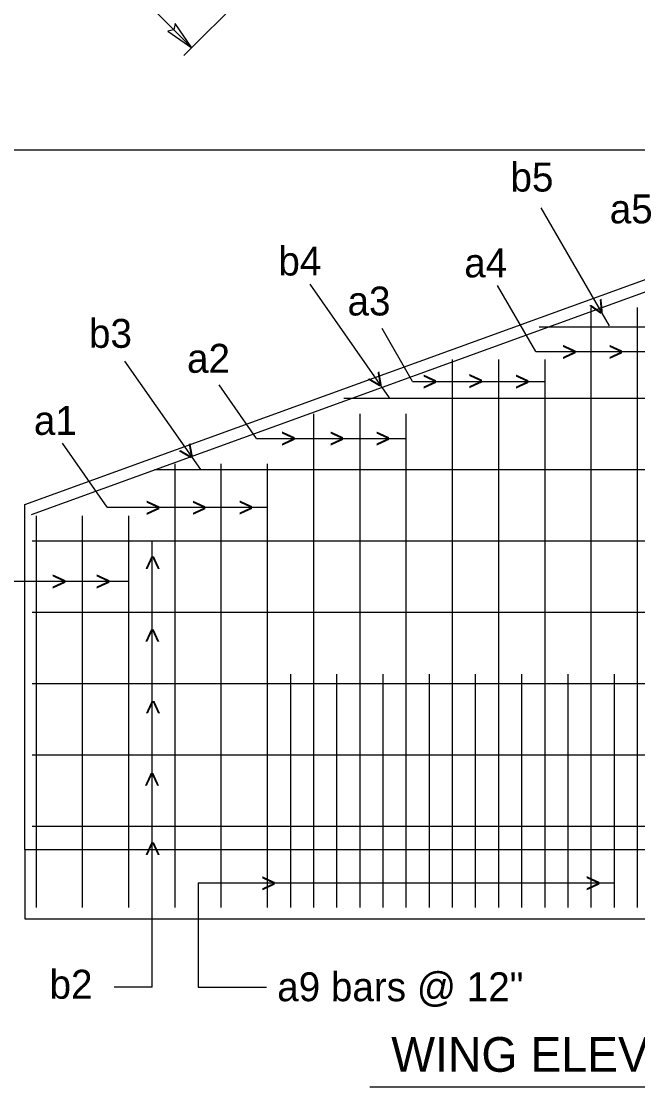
# Model space of a CAD drawing. Extents: x -0.08 to 2.83, y -0.03 to 1.92.
# Drawn here: x 0.368 to 0.6457, y 0.5697 to 1.0496 of the extents above; entities that cross this region are included whole.
import ezdxf

# ---------------------------------------------------------------- set-up
doc = ezdxf.new("R2010")
doc.units = 0
for name, color, linetype in [('50', 7, 'Continuous'), ('51', 7, 'Continuous'), ('54', 7, 'Continuous'), ('55', 7, 'Continuous'), ('57', 7, 'Continuous')]:
    doc.layers.add(name, color=color, linetype=linetype)

msp = doc.modelspace()

# ---------------------------------------------------------------- linework, layer by layer
at = {"layer": '50'}
for p, q in [((0.36955, 0.83186), (0.80997, 0.99159)), ((0.37249, 0.82739), (0.81676, 0.98851)), ((0.36955, 0.67649), (0.36955, 0.83186)), ((0.36955, 0.67649), (0.36955, 0.64524)), ((0.36955, 0.67649), (0.91992, 0.67649)), ((0.36955, 0.64524), (0.88809, 0.64524))]:
    msp.add_line(p, q, dxfattribs=at)
at = {"layer": '51'}
for p, q in [((0.62476, 0.65044), (0.62476, 0.92069)), ((0.64559, 0.65044), (0.64559, 0.92069)), ((0.81864, 0.91172), (0.60129, 0.91172)), ((0.56226, 0.65044), (0.56226, 0.89728)), ((0.58309, 0.65044), (0.58309, 0.89728)), ((0.60393, 0.65044), (0.60393, 0.89728)), ((0.81864, 0.8796), (0.51335, 0.8796)), ((0.49976, 0.65044), (0.49976, 0.87278)), ((0.52059, 0.65044), (0.52059, 0.87278)), ((0.54143, 0.65044), (0.54143, 0.87278)), ((0.43726, 0.65044), (0.43726, 0.85016)), ((0.45809, 0.65044), (0.45809, 0.85016)), ((0.47893, 0.65044), (0.47893, 0.85016)), ((0.81864, 0.84749), (0.42799, 0.84749)), ((0.37476, 0.65044), (0.37476, 0.82688)), ((0.39559, 0.65044), (0.39559, 0.82688)), ((0.41643, 0.65044), (0.41643, 0.82688)), ((0.81864, 0.81537), (0.37281, 0.81537)), ((0.81864, 0.78324), (0.37281, 0.78324)), ((0.48934, 0.65044), (0.48934, 0.75553)), ((0.51018, 0.65044), (0.51018, 0.75553)), ((0.53101, 0.65044), (0.53101, 0.75553)), ((0.55184, 0.65044), (0.55184, 0.75553)), ((0.57268, 0.65044), (0.57268, 0.75553)), ((0.59351, 0.65044), (0.59351, 0.75553)), ((0.61434, 0.65044), (0.61434, 0.75553)), ((0.63518, 0.65044), (0.63518, 0.75553)), ((0.81864, 0.75113), (0.37281, 0.75113)), ((0.81864, 0.71901), (0.37281, 0.71901)), ((0.81864, 0.68689), (0.37281, 0.68689))]:
    msp.add_line(p, q, dxfattribs=at)
at = {"layer": '54'}
msp.add_lwpolyline([(0.44481, 1.03767), (0.4373, 1.04853), (0.43669, 1.04579), (0.43403, 1.04505)], close=True, dxfattribs=at)
at = {"layer": '55'}
for p, q in [((0.32327, 1.1592), (0.44481, 1.03767)), ((0.49826, 1.09112), (0.44123, 1.03409)), ((0.79701, 0.99159), (0.27695, 0.99159)), ((0.63299, 0.91234), (0.60224, 0.96558)), ((0.53391, 0.87999), (0.49814, 0.93109)), ((0.59977, 0.90078), (0.58259, 0.93055)), ((0.54424, 0.88736), (0.53053, 0.91112)), ((0.59977, 0.90078), (0.66659, 0.90078)), ((0.44883, 0.84765), (0.41465, 0.89648)), ((0.474, 0.86169), (0.45709, 0.88584)), ((0.54424, 0.88736), (0.60393, 0.88736)), ((0.40664, 0.83074), (0.3865, 0.8595)), ((0.474, 0.86169), (0.54143, 0.86169)), ((0.40664, 0.83074), (0.47878, 0.83074)), ((0.42697, 0.61445), (0.42697, 0.81537)), ((0.34383, 0.79741), (0.41597, 0.79741)), ((0.44764, 0.6615), (0.44764, 0.61445)), ((0.44764, 0.6615), (0.63518, 0.6615)), ((0.42697, 0.61445), (0.40988, 0.61445)), ((0.44764, 0.61445), (0.47843, 0.61445))]:
    msp.add_line(p, q, dxfattribs=at)
at = {"layer": '57'}
msp.add_line((0.52505, 0.56966), (0.74916, 0.56966), dxfattribs=at)

# ---------------------------------------------------------------- texts
at = {"layer": '55'}
for height, rotation, p in [(0.00867, 299.9951, (0.62274, 0.92144)), (0.00867, 299.9951, (0.62274, 0.92144)), (0.00867, 299.9951, (0.62274, 0.92144)), (0.00867, 299.9951, (0.62274, 0.92144)), (0.00867, 304.992, (0.52289, 0.88818)), (0.00867, 304.992, (0.52289, 0.88818)), (0.00867, 304.992, (0.52289, 0.88818)), (0.00867, 304.992, (0.52289, 0.88818)), (0.00867, 304.992, (0.43781, 0.85584)), (0.00867, 304.992, (0.43781, 0.85584)), (0.00868, 90, (0.4313, 0.80235)), (0.00868, 90, (0.4313, 0.80235)), (0.00868, 90, (0.43116, 0.7695)), (0.00868, 90, (0.43116, 0.7695)), (0.00868, 90, (0.43145, 0.73725)), (0.00868, 90, (0.43145, 0.73725)), (0.00868, 90, (0.43101, 0.70471)), (0.00868, 90, (0.43101, 0.70471)), (0.00868, 90, (0.43129, 0.67352)), (0.00868, 90, (0.43129, 0.67352))]:
    msp.add_text('>', height=height, rotation=rotation, dxfattribs=at).set_placement(p)
for p in [(0.61147, 0.89649), (0.61147, 0.89649), (0.63244, 0.89649), (0.63244, 0.89649), (0.54861, 0.88313), (0.54861, 0.88313), (0.56932, 0.88335), (0.56932, 0.88335), (0.59025, 0.88313), (0.59025, 0.88313), (0.48489, 0.85747), (0.48489, 0.85747), (0.50674, 0.85747), (0.50674, 0.85747), (0.52744, 0.85747), (0.52744, 0.85747), (0.42395, 0.82629), (0.42395, 0.82629), (0.44473, 0.82629), (0.44473, 0.82629), (0.46576, 0.8264), (0.46576, 0.8264), (0.38157, 0.79309), (0.38157, 0.79309), (0.40138, 0.79309), (0.40138, 0.79309), (0.47594, 0.65712), (0.47594, 0.65712), (0.62216, 0.65717), (0.62216, 0.65717)]:
    msp.add_text('>', height=0.00868, dxfattribs=at).set_placement(p)
at = {"layer": '57'}
for s, height, p in [('b5', 0.013017, (0.58835, 0.97288)), ('a5', 0.013017, (0.63308, 0.95855)), ('b4', 0.013017, (0.48379, 0.93507)), ('a4', 0.013017, (0.56754, 0.93424)), ('a3', 0.013017, (0.51495, 0.91706)), ('b3', 0.013017, (0.39846, 0.90249)), ('a2', 0.013017, (0.44264, 0.89125)), ('a1', 0.013017, (0.37365, 0.86328)), ('b2', 0.013017, (0.3807, 0.6093)), ('a9 bars @ 12"', 0.0130167, (0.48327, 0.60817)), ('WING ELEVATION', 0.015625, (0.53466, 0.57637))]:
    msp.add_text(s, height=height, dxfattribs=at).set_placement(p)

doc.saveas('drawing.dxf')
